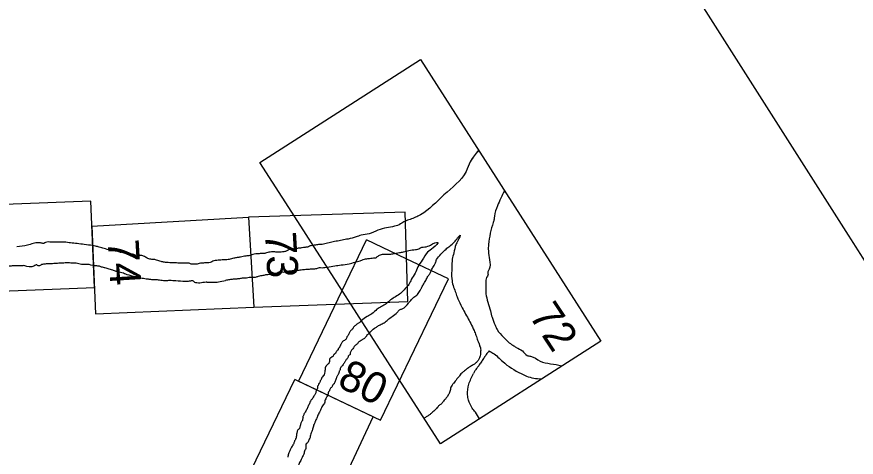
# Model space of a CAD drawing. Extents: x 3962991 to 3983549, y 181631 to 204078.
# Drawn here: x 3971302 to 3972884, y 187238 to 188068 of the extents above; entities that cross this region are included whole.
import ezdxf

# ---------------------------------------------------------------- set-up
doc = ezdxf.new("R2010")
doc.units = 0
doc.layers.add('V-ANNO-NPLT', color=7, linetype='Continuous')
doc.layers.add('V-GRID-FRAM', color=7, linetype='Continuous')

msp = doc.modelspace()

# ---------------------------------------------------------------- linework, layer by layer
at = {"layer": 'V-ANNO-NPLT'}
for p, q in [((3971739.2, 187690), (3971749.2, 187520.8)), ((3972174.5, 187310), (3972166.9, 187322.4))]:
    msp.add_line(p, q, dxfattribs=at)
for points in [[(3971760.7, 187793.6), (3972063.1, 187987.3), (3972403.3, 187456.6), (3972101.1, 187262.7)], [(3971826.6, 187690.9), (3971760.7, 187793.6)], [(3971442.2, 187720.7), (3971165, 187709.6)], [(3971448.9, 187557.6), (3971442.2, 187720.7)], [(3971165, 187709.6), (3971144, 187545.5), (3971448.9, 187557.6)], [(3971739.2, 187690), (3971749.2, 187520.8), (3972039.5, 187531.2), (3972034.7, 187699.4)], [(3972034.7, 187699.4), (3971739.2, 187690)], [(3971444.1, 187673.4), (3971739.2, 187690)], [(3972023.1, 187384.4), (3971826.6, 187690.9)], [(3971444.1, 187673.4), (3971450.9, 187508.1), (3971749.2, 187520.8)], [(3971915.7, 187552.2), (3971961.4, 187647.5)], [(3972036.3, 187611.9), (3971961.7, 187647.3)], [(3971832.3, 187381.6), (3971987.9, 187307.4), (3972115.8, 187574.2), (3972036.3, 187611.9)], [(3971833.8, 187381.4), (3971915.7, 187552.2)], [(3971697.2, 187115.4), (3971826.6, 187384.3)], [(3971974.4, 187313.8), (3971826.6, 187384.3)], [(3972101.1, 187262.7), (3972023.1, 187384.4)], [(3971697.2, 187115.4), (3971847.5, 187043.4), (3971974.4, 187313.8)]]:
    msp.add_lwpolyline(points, dxfattribs=at)
for points in [[(3972172.8, 187816.4), (3972157.2, 187794.9), (3972149.2, 187776.7), (3972107.4, 187732.1), (3972063.3, 187694.8), (3972043.7, 187685.8)], [(3972172.8, 187816.3), (3972157.2, 187794.9), (3972149.2, 187776.7), (3972107.4, 187732.1), (3972063.3, 187694.8), (3972043.7, 187685.8)], [(3972221.5, 187740.2), (3972208.3, 187711.6), (3972202.6, 187692.4), (3972202.1, 187686.2), (3972200.5, 187680.4), (3972191.5, 187639), (3972191.2, 187626.6), (3972193.4, 187609.7), (3972192.6, 187592.1), (3972190.3, 187587.2), (3972190.4, 187581), (3972188, 187576.5), (3972186.2, 187565.6), (3972186.7, 187546), (3972195, 187513.6), (3972198.1, 187501.5), (3972203.8, 187486.8), (3972207.9, 187478.3), (3972220.1, 187463.5), (3972230.7, 187453.4), (3972239.5, 187447.6), (3972243.9, 187444.6), (3972255.3, 187438), (3972264.4, 187429.4), (3972270.7, 187428.1), (3972288.6, 187419), (3972328.9, 187409.9), (3972330, 187409.5)], [(3972043.7, 187685.8), (3972033.8, 187682.4), (3972025.9, 187677.5), (3972014.1, 187673), (3971999.4, 187670.3), (3971983.1, 187665.7), (3971966.3, 187659), (3971951.6, 187656.3), (3971941.8, 187653), (3971926.8, 187649.1), (3971915.6, 187646.9), (3971904.1, 187644.8), (3971893.7, 187642.5), (3971888.3, 187641), (3971877.7, 187639), (3971869.1, 187638.2), (3971861.2, 187636.8)], [(3971967.1, 187471.4), (3971976.8, 187481), (3971981.4, 187483.8), (3971987.4, 187487.5), (3971995, 187491.3), (3971998.8, 187494), (3972002, 187496.7), (3972009.7, 187503), (3972019.4, 187510.8), (3972023.8, 187515.4), (3972028.9, 187517.6), (3972040.5, 187528.1), (3972044.8, 187533.4), (3972050.9, 187539.4), (3972057.8, 187544.5), (3972062.4, 187551.9), (3972064.9, 187556.7), (3972068.4, 187562.8), (3972073.2, 187570.9), (3972077.1, 187578.1), (3972080.8, 187583.6), (3972084.8, 187592.2), (3972088.8, 187599), (3972091.5, 187604.3), (3972093.7, 187610.2), (3972101.9, 187620.7), (3972111.4, 187630.2), (3972118.3, 187635.4), (3972127, 187643.4), (3972133.3, 187651.2), (3972137.9, 187656.3), (3972134.3, 187647), (3972129.8, 187638.2), (3972126, 187622.8), (3972123.2, 187611.1), (3972122.2, 187595.1), (3972122.3, 187574.2), (3972124.8, 187561.2), (3972128.9, 187550.1), (3972132.2, 187540.3), (3972139.2, 187524.6), (3972145, 187513.7), (3972151.6, 187501.4), (3972157.9, 187489.8), (3972164.3, 187476.5), (3972167.8, 187467.7), (3972169.5, 187462.7)], [(3971445.5, 187636.8), (3971429.7, 187638.6), (3971416, 187640.5), (3971403.9, 187641.7), (3971392.1, 187643.1), (3971378, 187643.1), (3971367.6, 187643.2), (3971356.7, 187642.5), (3971353.3, 187640.9), (3971346.8, 187641.8), (3971342.8, 187642.1), (3971333.4, 187640.6), (3971322.3, 187637.5), (3971302.4, 187634.5)], [(3971598.7, 187604), (3971587.9, 187604.6), (3971580.8, 187605.3), (3971574.4, 187606.5), (3971565.8, 187609.5), (3971559, 187610.5), (3971551, 187611.8), (3971545, 187614.8), (3971537.8, 187618.1), (3971530.8, 187617.8), (3971520.5, 187620.3), (3971511.3, 187621.8), (3971503.6, 187624.3), (3971499.3, 187623.7), (3971493.4, 187625.8), (3971478, 187628.1), (3971467.2, 187631.3), (3971457.9, 187633.8), (3971450.7, 187635.6), (3971445.5, 187636.8)], [(3971861.2, 187636.8), (3971858.6, 187636.6), (3971855, 187636.1), (3971852.7, 187635.1), (3971850.8, 187634), (3971847.3, 187633.5), (3971844.5, 187633.1), (3971840.5, 187632.7), (3971837.4, 187632.1), (3971832.9, 187631.9), (3971829.7, 187630.8), (3971823.8, 187630.6), (3971820.5, 187629.8), (3971815.8, 187629), (3971811.6, 187626.9), (3971805.9, 187625.1), (3971800.7, 187624.4), (3971795.3, 187624.1), (3971790.9, 187624.4), (3971787.1, 187625), (3971782.2, 187624.6), (3971777.4, 187624.2), (3971773.2, 187623.3), (3971769.7, 187622), (3971765.7, 187621.6), (3971761.4, 187621.6), (3971757.4, 187621.2), (3971752.8, 187621), (3971747, 187620), (3971741.8, 187618.1), (3971733.9, 187617), (3971728.9, 187616.1), (3971723.9, 187615.1)], [(3971887.6, 187595.7), (3971901.8, 187598.4), (3971913.5, 187600.1), (3971928.6, 187602.2), (3971939.6, 187605.3), (3971949.6, 187607.9), (3971955.3, 187610.2), (3971964.3, 187612.2), (3971974.9, 187613.3), (3971979, 187613.9), (3971983.3, 187616.8), (3971989.6, 187619.8), (3971998.2, 187620.5), (3972003.8, 187620.3), (3972011.4, 187621.3), (3972023.7, 187623.5), (3972031.4, 187624.9), (3972041.1, 187627.4), (3972053.8, 187629.3), (3972062.3, 187631.7), (3972063.2, 187632.3), (3972074.2, 187634.6), (3972084.3, 187638.9), (3972090.6, 187641.9), (3972095.8, 187642.4), (3972087.2, 187632.6), (3972076.8, 187624.4), (3972066.6, 187609.2), (3972058.3, 187596.7), (3972053.2, 187584.4), (3972045.9, 187572.6), (3972041.5, 187563.6), (3972034.6, 187555.6), (3972025.6, 187546.5), (3972006.9, 187534.1), (3971998.5, 187527.1), (3971990.1, 187521.8), (3971981.3, 187516.5), (3971971.5, 187508), (3971962.8, 187502.8), (3971951.6, 187495)], [(3971316, 187598.9), (3971307.2, 187598.5), (3971297.9, 187598.4), (3971289.9, 187598), (3971284.3, 187597.8), (3971276.2, 187597.7), (3971265.8, 187596.7), (3971261.5, 187595.6), (3971256.4, 187595.3), (3971250.9, 187595.6), (3971243.3, 187594.7), (3971240.5, 187594.6), (3971236.2, 187595.6), (3971232.4, 187596.5), (3971229.6, 187598.4), (3971223.6, 187598.8), (3971218.9, 187599.2), (3971210.6, 187600.6), (3971206.5, 187601.4), (3971202, 187600.7), (3971194.9, 187601.6), (3971189.5, 187602.4)], [(3971469.9, 187594.5), (3971462.3, 187596.3), (3971456.9, 187597.9), (3971449, 187598.4), (3971435.3, 187601.3), (3971424.1, 187601), (3971414.3, 187603.6), (3971406.9, 187603.4), (3971402, 187604.2), (3971398.7, 187604.3), (3971388.4, 187603.4), (3971379.3, 187603.2), (3971370, 187602.4), (3971361.5, 187602), (3971354.1, 187601.8), (3971347.6, 187600), (3971342.5, 187598.5), (3971339.9, 187600.1), (3971337.8, 187599.9), (3971334.7, 187598), (3971316, 187598.9)], [(3971723.9, 187615.1), (3971717.8, 187614), (3971711.2, 187612.9), (3971702.7, 187610.7), (3971694.3, 187609.8), (3971684.4, 187609.2), (3971679.2, 187608.6), (3971673.8, 187607.8), (3971666.7, 187604.7), (3971658.1, 187604.1), (3971650.8, 187603.4), (3971646.2, 187603.2), (3971642.1, 187601.5), (3971636.4, 187601.8), (3971630.8, 187601.8), (3971628.8, 187603.1), (3971623, 187603.4), (3971617.5, 187603.4), (3971610.6, 187603.4), (3971605.7, 187603.8), (3971601.2, 187604.1), (3971598.7, 187604)], [(3971620.1, 187569), (3971602, 187570), (3971590.7, 187570.7), (3971581.7, 187570.3), (3971571.7, 187571.4), (3971563, 187572.2), (3971555.1, 187572.5), (3971548.9, 187573.3), (3971538.7, 187574.8), (3971526, 187577.8), (3971510.7, 187581.8), (3971500.7, 187585.4), (3971490, 187587.6), (3971483.3, 187590.2), (3971474.4, 187592.9), (3971471.1, 187594)], [(3971887.6, 187595.7), (3971878.2, 187594.4), (3971872.1, 187594.5), (3971865.6, 187592.7), (3971857.8, 187592.1), (3971849.2, 187591.5), (3971840.6, 187590.9), (3971835.9, 187590.2), (3971827, 187589.4), (3971819.7, 187588.7), (3971813.4, 187587.9), (3971808.3, 187586.4), (3971803.2, 187586.3), (3971798.5, 187586.4), (3971794.8, 187586.2), (3971790.9, 187583.4), (3971786.4, 187583.2), (3971782.2, 187582.3), (3971778.1, 187581.9), (3971772.8, 187581.6), (3971766.4, 187580.2), (3971757.5, 187578.6), (3971752, 187576.5), (3971745.9, 187576.6)], [(3971660.9, 187567.8), (3971659.2, 187567.6), (3971653.2, 187566.9), (3971647.7, 187566.1), (3971641.6, 187566.2), (3971638.1, 187567), (3971635.3, 187569.6), (3971629.6, 187569.9), (3971625.4, 187569), (3971620.1, 187569)], [(3971660.9, 187567.8), (3971672.9, 187567.9), (3971682.5, 187568.2), (3971695.8, 187571)], [(3971745.9, 187576.6), (3971740.4, 187576.6), (3971735.1, 187575.5), (3971727.3, 187575), (3971720.2, 187574), (3971713.7, 187573.4), (3971706.9, 187572.7), (3971699.5, 187571.5), (3971695.9, 187571), (3971695.8, 187571)], [(3971951.6, 187495), (3971947.7, 187491.1), (3971945.3, 187489.6), (3971943.6, 187488.3), (3971942.2, 187486.9), (3971940.6, 187485.9), (3971939.1, 187484.7), (3971937.6, 187483.5), (3971936.3, 187481.6), (3971935.5, 187479.7), (3971933.6, 187478), (3971931.6, 187475.7), (3971930.4, 187474.1), (3971928.9, 187471.5), (3971927.7, 187469.3), (3971927, 187467.8), (3971925.2, 187465.3), (3971924.2, 187463.3), (3971921.4, 187458.8), (3971918.4, 187456.9), (3971916.5, 187455.7)], [(3971967.1, 187471.4), (3971964.7, 187469.7), (3971961.8, 187467), (3971960.7, 187465.1), (3971958.9, 187463.1), (3971957.6, 187461.4), (3971955.3, 187460.3), (3971953.2, 187459), (3971951.2, 187457.5), (3971948.1, 187455.9), (3971946.3, 187454.5), (3971945, 187452.8), (3971943.6, 187450.7), (3971940.7, 187448.7), (3971938.2, 187446.5), (3971936.8, 187443.6), (3971934.5, 187441), (3971932.5, 187438), (3971931.5, 187435.9), (3971930.8, 187433.2), (3971930.8, 187431.4), (3971929, 187430), (3971927.6, 187428.8), (3971927, 187427), (3971926.2, 187425.3), (3971924.9, 187423.6), (3971923.5, 187421.6), (3971921.8, 187419.1), (3971920.9, 187417.3), (3971919.3, 187415.2), (3971915.3, 187409.2), (3971912.1, 187404.8), (3971911.6, 187402.2), (3971910.5, 187400.7), (3971910.1, 187398.4)], [(3972169.5, 187462.7), (3972170.7, 187458.3), (3972173.4, 187452.7), (3972173.8, 187451), (3972174.8, 187447.5), (3972176.3, 187444.1), (3972176.7, 187439.7), (3972176.6, 187435.7), (3972176.1, 187431.3), (3972175.1, 187426.9), (3972173.9, 187423.5), (3972171.7, 187419.7), (3972167.6, 187415.5), (3972164.9, 187413), (3972160.6, 187410.6), (3972155, 187407.1), (3972152.1, 187405.1), (3972146.4, 187400.6), (3972143.8, 187398.4)], [(3971911.2, 187446.3), (3971911, 187445.4), (3971910.2, 187444.4), (3971909.3, 187443.5), (3971908.3, 187442.1), (3971908.2, 187441.7), (3971907.9, 187440.4), (3971907.9, 187439.9), (3971906.8, 187439.5), (3971905.2, 187437.1), (3971903.9, 187435.2), (3971901.5, 187431.8), (3971900.4, 187431.7), (3971899.7, 187430.7), (3971898.9, 187428.8), (3971898.3, 187427.5), (3971897.6, 187427.2), (3971896.3, 187426.6)], [(3971916.5, 187455.7), (3971915.2, 187453.6), (3971913.9, 187451.2), (3971912.2, 187448.5), (3971911.2, 187446.3)], [(3972192.5, 187438.2), (3972187.2, 187431.1), (3972183.1, 187425.1), (3972178.6, 187418.5), (3972174.1, 187411.7), (3972169.8, 187405.9), (3972166, 187400.6), (3972163.2, 187395.2)], [(3972192.5, 187438.2), (3972199.7, 187434.1), (3972218.2, 187418.1), (3972253.1, 187395.2), (3972263.1, 187390.6), (3972290.8, 187385.5), (3972291.1, 187385.5)], [(3971896.3, 187426.6), (3971894.9, 187425.6), (3971893.8, 187425), (3971892.4, 187423.8), (3971892, 187422.5), (3971892.1, 187420.6), (3971891.9, 187419), (3971891.8, 187417.9), (3971890.7, 187415.2), (3971889.8, 187413.9), (3971888.7, 187412.9), (3971887.4, 187411.5), (3971886.3, 187410.6), (3971885.3, 187409.4), (3971884.3, 187408.3), (3971883.9, 187406.7)], [(3971910.1, 187398.4), (3971908.9, 187394.7), (3971907.9, 187393.4), (3971907.1, 187391.8), (3971905.4, 187389.3), (3971904.7, 187387.6), (3971903.8, 187383.9), (3971901.3, 187377.9), (3971900.3, 187376.1), (3971898.4, 187374.9), (3971897.4, 187372.6), (3971895.9, 187369.9), (3971894.6, 187368.2), (3971892.8, 187366.8), (3971891.9, 187363.9), (3971890.9, 187362.1), (3971889.8, 187360.6), (3971889.1, 187356.9), (3971887.9, 187354.1), (3971887.1, 187352.1), (3971885.5, 187349.4), (3971884.8, 187347.7), (3971883.1, 187343.8), (3971882.2, 187339.4), (3971879.8, 187336.2), (3971877.5, 187332.7), (3971875.4, 187328.1), (3971874.1, 187325), (3971872, 187320.7), (3971869.8, 187317.1), (3971869.2, 187314.6)], [(3971883.9, 187406.7), (3971883.4, 187403.6), (3971883.3, 187400.6), (3971882.4, 187396.4), (3971881.9, 187393.8), (3971881.7, 187392.8)], [(3972143.8, 187398.4), (3972141.2, 187396.3), (3972138.1, 187392.8), (3972135.9, 187389.9), (3972134.3, 187387.7), (3972132, 187385.3), (3972128.9, 187380.9), (3972126, 187377.3), (3972122.7, 187373.5), (3972120.6, 187369.9), (3972119.8, 187365.4), (3972118.7, 187361.4), (3972117.3, 187358), (3972115.6, 187355.4), (3972115, 187354.1)], [(3971881.7, 187392.8), (3971881.6, 187392.5), (3971880.5, 187391.6), (3971879.7, 187390.8), (3971877.6, 187387.8), (3971875.9, 187384.2), (3971874.5, 187381.5), (3971873.8, 187379.1), (3971872.6, 187377.3), (3971870.2, 187373), (3971869, 187370), (3971869, 187367.2), (3971867.7, 187365.3), (3971866.9, 187363.1), (3971866.4, 187362), (3971866.1, 187359.3), (3971864.8, 187356.5), (3971863.2, 187354.2), (3971859.2, 187347.5), (3971856, 187343.6), (3971854.1, 187338.6), (3971852.5, 187335.6), (3971851.2, 187332.3), (3971848.1, 187326.2), (3971846, 187322.7), (3971844.3, 187320), (3971842, 187315.2), (3971841.5, 187313.8), (3971841.9, 187311.8), (3971841, 187309.1)], [(3972166.9, 187322.4), (3972160.7, 187330.4), (3972154, 187345), (3972152.1, 187355.4), (3972154.4, 187375.3), (3972163.2, 187395.2)], [(3972115, 187354.1), (3972112.8, 187350.7), (3972109.3, 187346.2), (3972106.9, 187343.6), (3972105.2, 187341.4), (3972103.2, 187338.8), (3972098.4, 187335.4), (3972094.8, 187331.2), (3972092, 187328.3), (3972089.8, 187325.8), (3972083.3, 187320.2), (3972079.3, 187316.8), (3972076.5, 187315)], [(3971869.2, 187314.6), (3971866.3, 187308.4), (3971864.8, 187304.6), (3971863.9, 187302.2), (3971861.9, 187297.8), (3971861, 187294), (3971859.6, 187290.2), (3971859.3, 187288.2), (3971857.4, 187283.6), (3971856, 187279.2), (3971855.1, 187275), (3971853.7, 187271.5), (3971852, 187268.4), (3971850.7, 187265.3), (3971849.4, 187264.2), (3971847.2, 187261), (3971847.2, 187258.1), (3971846.9, 187253.8), (3971845.6, 187250.7), (3971844.2, 187247.2), (3971843.3, 187243.4), (3971841.1, 187238.8), (3971839.2, 187234.7), (3971837.7, 187231.4), (3971835.5, 187227.4), (3971834.3, 187224), (3971832.8, 187221.3), (3971832.3, 187218.7)], [(3971841, 187309.1), (3971840.9, 187306.6), (3971839.9, 187305.4), (3971838.4, 187303), (3971837.6, 187300.9)], [(3972076.5, 187315), (3972074.2, 187313.5), (3972072.7, 187312.6), (3972070.2, 187310.9)], [(3971835.5, 187292.5), (3971835.2, 187291.9), (3971834, 187290.6), (3971833.1, 187290.1), (3971831.6, 187288.2), (3971830.8, 187285.7), (3971830.3, 187283.6), (3971829.6, 187281.4), (3971829.5, 187279.6), (3971829.4, 187277.5), (3971828.9, 187275.4), (3971828.8, 187273.6), (3971828, 187272.2), (3971826.9, 187270), (3971826.1, 187268.4), (3971825.1, 187265.7), (3971824.4, 187263.2), (3971823.4, 187261.4), (3971822.5, 187260), (3971820.2, 187256.5), (3971819.1, 187254), (3971817.4, 187251.5)], [(3971837.6, 187300.9), (3971837.2, 187299.2), (3971836.6, 187297.1), (3971836, 187294.7), (3971835.5, 187292.5)], [(3971817.4, 187251.5), (3971816.5, 187248.1), (3971815.3, 187245.9), (3971814.2, 187242.3), (3971813.5, 187239.2), (3971813.2, 187237.6)]]:
    msp.add_spline(points, degree=3, dxfattribs=at)
at = {"layer": 'V-GRID-FRAM'}
msp.add_lwpolyline([(3973881.1, 201670.7), (3982001.8, 189003.7), (3974929.2, 184418.3), (3966825.4, 197159.8), (3973881.1, 201670.7)], dxfattribs=at)

# ---------------------------------------------------------------- texts
at = {"layer": 'V-ANNO-NPLT'}
for s, rotation, p in [('73', 273.3756, (3971770.1, 187661)), ('74', 273.3756, (3971473.6, 187647)), ('72', 303.3756, (3972266.3, 187504.9)), ('80', 333.3756, (3971903.9, 187372.6))]:
    msp.add_text(s, height=58.5, rotation=rotation, dxfattribs=at).set_placement(p)

doc.saveas('drawing.dxf')
